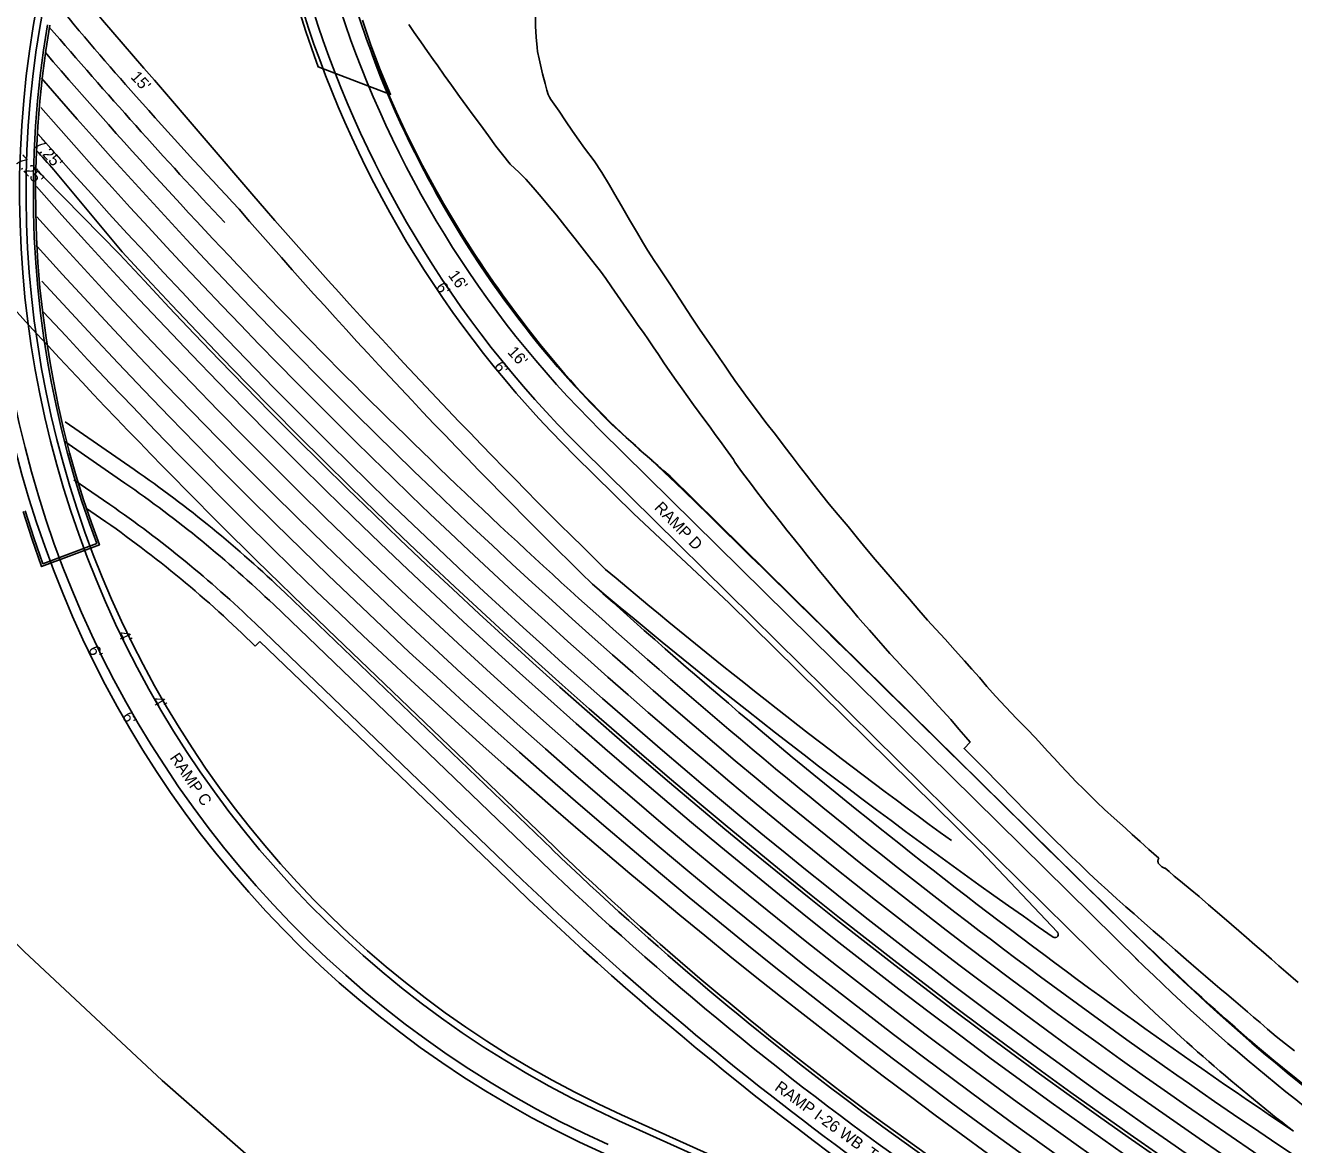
# Model space of a CAD drawing. Extents: x -5665 to 1997148, y 4 to 812485.
# Drawn here: x 1971429 to 1972202, y 795072 to 795754 of the extents above; entities that cross this region are included whole.
import ezdxf

# ---------------------------------------------------------------- set-up
doc = ezdxf.new("R2010")
doc.units = 0
for name, color, linetype in [('BR_CONCRETE', 7, 'Continuous'), ('RD_EX_RailRoad', 7, 'Continuous'), ('RD_EX_Road', 7, 'Continuous'), ('RD_PD_ALT1_TrvlWay', 7, 'Continuous'), ('RD_PD_Final_LnLine', 7, 'Continuous'), ('RD_PD_MedBWall', 7, 'Continuous'), ('RD_PD_PaveShd', 7, 'Continuous'), ('RD_SHT_TX', 7, 'Continuous')]:
    doc.layers.add(name, color=color, linetype=linetype)

msp = doc.modelspace()

# ---------------------------------------------------------------- linework, layer by layer
at = {"layer": 'BR_CONCRETE'}
for points in [[(1971634.55, 795757.25), (1971639.81, 795742.09), (1971645.43, 795727.05), (1971651.77, 795712.01), (1971607.64, 795728.69), (1971605.06, 795735.74), (1971600.01, 795750.42), (1971595.33, 795765.23)], [(1971427.6, 795457.68), (1971432.96, 795441.15), (1971438.9, 795424.1), (1971474.23, 795437.31), (1971469.3, 795450.73), (1971464.49, 795464.87), (1971460.05, 795479.14), (1971455.99, 795493.52), (1971452.32, 795508), (1971449.02, 795522.58), (1971446.11, 795537.24), (1971444.07, 795548.37), (1971441.63, 795563.56), (1971439.59, 795578.81), (1971437.93, 795594.1), (1971436.66, 795609.43), (1971435.79, 795624.79), (1971435.32, 795640.17), (1971435.23, 795655.56), (1971435.3, 795661.39), (1971435.74, 795676.92), (1971436.58, 795692.43), (1971437.81, 795707.91), (1971439.43, 795723.36), (1971441.45, 795738.75), (1971443.85, 795754.1)], [(1971428.84, 795458.07), (1971434.19, 795441.56), (1971439.69, 795425.78), (1971472.56, 795438.08), (1971468.07, 795450.29), (1971463.25, 795464.47), (1971458.8, 795478.77), (1971454.74, 795493.19), (1971451.05, 795507.7), (1971447.75, 795522.31), (1971444.83, 795537), (1971442.79, 795548.15), (1971440.35, 795563.37), (1971438.3, 795578.65), (1971436.63, 795593.98), (1971435.37, 795609.34), (1971434.49, 795624.74), (1971434.02, 795640.14), (1971433.93, 795655.56), (1971434, 795661.42), (1971434.44, 795676.97), (1971435.28, 795692.52), (1971436.52, 795708.03), (1971438.14, 795723.51), (1971440.16, 795738.94), (1971442.57, 795754.32)]]:
    msp.add_lwpolyline(points, dxfattribs=at)
at = {"layer": 'RD_EX_RailRoad'}
msp.add_lwpolyline([(1970768.64, 796132.97), (1970840.22, 796002.22), (1970871.33, 795945.04), (1970902.78, 795888.08), (1970934.57, 795831.3), (1970952.16, 795800.24), (1970967.81, 795773.45), (1970983.81, 795746.85), (1971000.15, 795720.46), (1971015.17, 795696.82), (1971080.56, 795598.9), (1971155.96, 795496.05), (1971262.73, 795364.94), (1971358.83, 795259.6), (1971428.31, 795189.39), (1971512.52, 795110.76), (1971575.1, 795055.94)], dxfattribs=at)
at = {"layer": 'RD_EX_Road'}
for points in [[(1972202.99, 795128.91), (1972197.53, 795133.14), (1972191.85, 795137.65), (1972186.64, 795142.05), (1972182.02, 795146.08), (1972178.11, 795149.44), (1972174.33, 795152.65), (1972170.09, 795156.24), (1972165.74, 795159.92), (1972161.68, 795163.37), (1972157.59, 795166.85), (1972153.17, 795170.6), (1972148.71, 795174.4), (1972144.52, 795178.02), (1972137.03, 795184.49), (1972130.15, 795190.47), (1972123.29, 795196.46), (1972116.91, 795202.04), (1972109.68, 795208.4), (1972105.18, 795212.33), (1972100.16, 795216.72), (1972094.76, 795221.51), (1972089.09, 795226.64), (1972083.34, 795231.93), (1972077.67, 795237.24), (1972072.22, 795242.41), (1972067.1, 795247.34), (1972062.06, 795252.25), (1972056.87, 795257.35), (1972051.98, 795262.19), (1972047.86, 795266.28), (1972043.68, 795270.47), (1972038.6, 795275.61), (1972032.58, 795281.75), (1972029.21, 795285.21), (1972025.59, 795288.94), (1972021.91, 795292.72), (1972014.91, 795299.86), (1972008.51, 795306.29), (1972001.53, 795313.25), (1972005.19, 795316.96), (1972002.54, 795320.11), (1971998.37, 795325.07), (1971993.46, 795330.77), (1971988.6, 795336.15), (1971983.74, 795341.44), (1971978.83, 795346.85), (1971973.91, 795352.22), (1971968.98, 795357.42), (1971964.33, 795362.3), (1971960.22, 795366.74), (1971956.27, 795371.11), (1971952.1, 795375.81), (1971947.88, 795380.6), (1971943.77, 795385.24), (1971939.83, 795389.73), (1971936.75, 795393.32), (1971932.4, 795398.47), (1971928.42, 795403.19), (1971924.47, 795407.9), (1971920.85, 795412.3), (1971917.2, 795416.78), (1971913.15, 795421.75), (1971909.19, 795426.63), (1971905.8, 795430.85), (1971902.3, 795435.25), (1971898.02, 795440.65), (1971893.51, 795446.33), (1971889.31, 795451.59), (1971885.43, 795456.44), (1971881.89, 795460.92), (1971878.52, 795465.27), (1971875.13, 795469.76), (1971871.8, 795474.18), (1971865.75, 795482.13), (1971861.78, 795487.75), (1971861.33, 795488.49), (1971860.83, 795489.47), (1971856.06, 795496.07), (1971852.88, 795500.39), (1971849.75, 795504.68), (1971846.59, 795509.01), (1971843.37, 795513.4), (1971840.02, 795517.96), (1971836.53, 795522.69), (1971833.05, 795527.52), (1971829.58, 795532.46), (1971825.94, 795537.62), (1971822.15, 795542.97), (1971818.5, 795548.23), (1971815.06, 795553.31), (1971811.91, 795558.01), (1971808.99, 795562.35), (1971805.96, 795566.73), (1971802.81, 795571.17), (1971799.84, 795575.37), (1971797.01, 795579.41), (1971793.78, 795584.1), (1971790.14, 795589.44), (1971786.52, 795594.71), (1971783.01, 795599.72), (1971779.71, 795604.17), (1971776.54, 795608.2), (1971772.84, 795612.94), (1971768.58, 795618.45), (1971764.38, 795623.83), (1971760.35, 795628.92), (1971756.54, 795633.73), (1971752.86, 795638.4), (1971748.51, 795643.69), (1971743.51, 795649.6), (1971738.68, 795655.21), (1971734.19, 795660.3), (1971730.28, 795664.27), (1971724.59, 795669.49), (1971719.94, 795675.3), (1971715.99, 795680.51), (1971711.46, 795686.64), (1971706.58, 795693.36), (1971702.21, 795699.33), (1971698.31, 795704.6), (1971693.86, 795710.69), (1971688.89, 795717.58), (1971684.51, 795723.68), (1971680.48, 795729.31), (1971677.72, 795733.24), (1971674.31, 795738.12), (1971670.25, 795743.95), (1971666.22, 795749.76), (1971662.88, 795754.58)], [(1972205.34, 795170.43), (1972197.82, 795176.94), (1972193.54, 795180.68), (1972188.95, 795184.68), (1972184.06, 795188.96), (1972178.86, 795193.5), (1972173.72, 795197.99), (1972168.99, 795202.09), (1972164.68, 795205.82), (1972157.2, 795212.24), (1972150.64, 795217.89), (1972144.82, 795222.88), (1972139.47, 795227.37), (1972134.7, 795231.25), (1972131.54, 795233.83), (1972129.7, 795235.37), (1972126.5, 795238.16), (1972124.22, 795240.18), (1972123.77, 795240.29), (1972123.33, 795240.44), (1972122.92, 795240.62), (1972122.51, 795240.83), (1972122.11, 795241.08), (1972121.29, 795241.76), (1972120.47, 795242.61), (1972120.17, 795243), (1972119.96, 795243.35), (1972119.85, 795243.66), (1972119.79, 795243.95), (1972119.76, 795244.24), (1972119.75, 795244.53), (1972119.77, 795244.81), (1972119.82, 795245.11), (1972119.92, 795245.45), (1972120.24, 795246.25), (1972114.21, 795251.7), (1972108.82, 795256.56), (1972104.07, 795260.83), (1972099.96, 795264.52), (1972092.98, 795270.79), (1972087.21, 795276.05), (1972082.42, 795280.53), (1972078.39, 795284.46), (1972074.45, 795288.4), (1972069.94, 795292.93), (1972064.15, 795298.92), (1972060.51, 795302.82), (1972056.39, 795307.3), (1972052.45, 795311.61), (1972047.16, 795317.37), (1972044.58, 795320.12), (1972040.17, 795324.7), (1972033.54, 795331.53), (1972026.91, 795338.48), (1972020.73, 795345.12), (1972015.38, 795351.08), (1972010.82, 795356.38), (1972006.33, 795361.52), (1972001.68, 795366.73), (1971996.17, 795372.85), (1971989.89, 795379.77), (1971984.26, 795385.97), (1971979.3, 795391.43), (1971973.96, 795397.47), (1971968.17, 795404.14), (1971962.7, 795410.47), (1971957.61, 795416.38), (1971952.52, 795422.33), (1971947.34, 795428.44), (1971942.04, 795434.79), (1971936.58, 795441.42), (1971930.73, 795448.45), (1971924.63, 795455.73), (1971919.26, 795462.24), (1971914.66, 795467.96), (1971910.09, 795473.8), (1971905.47, 795479.83), (1971901.04, 795485.62), (1971896.72, 795491.23), (1971891.86, 795497.52), (1971886.41, 795504.58), (1971880.69, 795512.03), (1971874.9, 795519.66), (1971869.84, 795526.43), (1971865.58, 795532.26), (1971861.76, 795537.62), (1971858.34, 795542.58), (1971855.34, 795546.97), (1971852.59, 795550.97), (1971849.13, 795555.95), (1971844.89, 795562.07), (1971840.23, 795568.86), (1971835.28, 795576.17), (1971830.33, 795583.66), (1971825.5, 795591.13), (1971821.22, 795597.69), (1971817.59, 795603.16), (1971814.74, 795607.47), (1971812.61, 795610.71), (1971810.75, 795613.53), (1971808.49, 795617.05), (1971805.44, 795622.13), (1971802.3, 795627.43), (1971797.51, 795635.58), (1971792.58, 795644.02), (1971788.48, 795651.04), (1971785.21, 795656.66), (1971780.67, 795664.39), (1971775.84, 795671.57), (1971770.08, 795679.26), (1971766.63, 795684.05), (1971762.76, 795689.57), (1971758.47, 795695.84), (1971754.48, 795701.72), (1971749.55, 795708.94), (1971748.61, 795710.29), (1971748.19, 795711), (1971747.78, 795711.96), (1971746.98, 795714.61), (1971745.95, 795718.68), (1971744.44, 795724.61), (1971742.34, 795733.65), (1971741.44, 795738.06), (1971741.15, 795740.48), (1971740.59, 795746.9), (1971740.15, 795753.55), (1971740.09, 795759.95)], [(1972208.47, 795108.39), (1972201.83, 795113.73), (1972195.78, 795118.63), (1972190.51, 795122.93), (1972185.36, 795127.2), (1972180.48, 795131.34), (1972177.35, 795133.99), (1972175.69, 795135.43), (1972172.24, 795138.43), (1972166.76, 795143.23), (1972160.87, 795148.41), (1972154.61, 795153.96), (1972150.83, 795157.37), (1972146.54, 795161.29), (1972141.73, 795165.71), (1972136.97, 795170.12), (1972132.83, 795173.98), (1972126.38, 795180.08), (1972121.57, 795184.71), (1972117.55, 795188.57), (1972112.98, 795192.96), (1972106.54, 795199.17), (1972102.69, 795202.91), (1972098.5, 795206.99), (1972093.98, 795211.42), (1972089.13, 795216.19), (1972084.21, 795221.04), (1972079.48, 795225.69), (1972074.93, 795230.14), (1972070.58, 795234.39), (1972066.25, 795238.62), (1972061.75, 795243.01), (1972057.09, 795247.57), (1972052.27, 795252.3), (1972047.12, 795257.36), (1972041.46, 795262.94), (1972035.3, 795269.02), (1972028.63, 795275.61), (1972021.63, 795282.54), (1972014.45, 795289.61), (1972007.11, 795296.83), (1971999.59, 795304.21), (1971992.01, 795311.63), (1971984.48, 795319.02), (1971977, 795326.36), (1971969.58, 795333.66), (1971962.15, 795340.97), (1971954.65, 795348.35), (1971947.08, 795355.78), (1971939.45, 795363.28), (1971931.75, 795370.85), (1971923.98, 795378.51), (1971916.13, 795386.25), (1971908.2, 795394.07), (1971900.36, 795401.81), (1971892.77, 795409.28), (1971885.44, 795416.49), (1971878.36, 795423.44), (1971871.13, 795430.52), (1971863.37, 795438.13), (1971855.05, 795446.28), (1971846.2, 795454.97), (1971837.83, 795463.17), (1971830.96, 795469.87), (1971825.61, 795475.08), (1971818.89, 795481.54), (1971814.43, 795485.78), (1971811.29, 795488.73), (1971806.89, 795492.7), (1971801.09, 795497.86), (1971795.5, 795502.84), (1971790.49, 795507.31), (1971786.74, 795510.76), (1971784.13, 795513.3), (1971781.27, 795516.16), (1971777.88, 795519.61), (1971773.54, 795524.14), (1971768.57, 795529.39), (1971765.38, 795532.78), (1971763.94, 795534.32), (1971761.71, 795536.78), (1971758.26, 795540.65), (1971753.61, 795545.97), (1971748.06, 795552.42), (1971743.48, 795557.86), (1971740.03, 795562.1), (1971736.92, 795566.03), (1971733.87, 795569.97), (1971729.99, 795575.04), (1971725.35, 795581.14), (1971721.23, 795586.62), (1971717.72, 795591.39), (1971714.02, 795596.58), (1971710.03, 795602.34), (1971705.82, 795608.6), (1971701.52, 795615.14), (1971697.87, 795620.85), (1971694.8, 795625.83), (1971691.16, 795631.84), (1971686.95, 795638.89), (1971683.25, 795645.2), (1971680.19, 795650.58), (1971677.45, 795655.56), (1971674.91, 795660.33), (1971672.24, 795665.39), (1971669.41, 795670.83), (1971666.52, 795676.52), (1971663.6, 795682.45), (1971660.63, 795688.56), (1971657.61, 795694.88), (1971654.54, 795701.62), (1971651.45, 795708.73), (1971648.49, 795715.79), (1971645.68, 795722.74), (1971643, 795729.69), (1971640.57, 795736.24), (1971639.23, 795739.89), (1971639.01, 795740.48)]]:
    msp.add_lwpolyline(points, dxfattribs=at)
at = {"layer": 'RD_PD_ALT1_TrvlWay'}
for p, q in [((1971779.64, 795507.29), (1972107.79, 795183.82)), ((1971453.08, 795500.31), (1971489.67, 795475.03)), ((1972094.93, 795174.03), (1971768.41, 795495.9)), ((1971458.6, 795477.05), (1971480.58, 795461.86)), ((1971580.47, 795400.88), (1971743.18, 795244.69)), ((1971569.39, 795389.34), (1971732.1, 795233.15)), ((1971790.98, 795086.26), (1972145.53, 794926.28))]:
    msp.add_line(p, q, dxfattribs=at)
for centre, radius, start, end in [((1972226.58, 795960.7), 652.66, 167.91315, 225.41147), ((1972226.58, 795960.7), 636.66, 170.70317, 225.41147), ((1972046.23, 795651.96), 636.62, 156.21044, 245.71509), ((1972046.23, 795651.96), 620.62, 156.21044, 245.71509), ((1972855.69, 796921.19), 1820, 219.26396, 221.68841), ((1974296, 798203.94), 3748.72, 221.68841, 223.11151), ((1974296, 798203.94), 3808.72, 221.35099, 236.97136), ((1974296, 798203.94), 3830.72, 221.69794, 243.9112), ((1974398.08, 798103.05), 3757.03, 220.92379, 225.71558), ((1974296, 798203.94), 3878.72, 222.58465, 241.30888), ((1971073.56, 794872.81), 732, 46.17145, 55.35655), ((1971073.56, 794872.81), 716, 46.17145, 55.35655), ((1974296, 798203.94), 3760.72, 227.90275, 236.17378), ((1973117.1, 796675.98), 1984, 226.17145, 243.9112), ((1973117.1, 796675.98), 2000, 226.17145, 241.45743), ((1972948.57, 796040.02), 1200, 225.41147, 237.12717), ((1972948.57, 796040.02), 1216, 225.41147, 232.15338)]:
    msp.add_arc(centre, radius, start, end, dxfattribs=at)
at = {"layer": 'RD_PD_Final_LnLine'}
for radius, start, end in [(3760.72, 220.66614, 223.11151), (3772.72, 220.82697, 227.89927), (3784.72, 220.98219, 236.97136), (3796.72, 221.18106, 236.97136), (3842.72, 221.90557, 243.9112), (3854.72, 222.10892, 243.9112), (3866.72, 222.36815, 243.9112), (3772.72, 227.89927, 236.97136)]:
    msp.add_arc((1974296, 798203.94), radius, start, end, dxfattribs=at)
at = {"layer": 'RD_PD_MedBWall'}
for p, q in [((1971486.53, 795614.58), (1971440.84, 795660.92)), ((1971446.44, 795665.91), (1971488.03, 795615.91))]:
    msp.add_line(p, q, dxfattribs=at)
for radius, start in [(3820.72, 222.66541), (3818.72, 222.66592)]:
    msp.add_arc((1974296, 798203.94), radius, start, 243.9112, dxfattribs=at)
at = {"layer": 'RD_PD_PaveShd'}
for p, q in [((1971507.76, 795720.72), (1971568.41, 795649.85)), ((1971453.36, 795512.27), (1971495.36, 795483.25)), ((1971764.19, 795491.62), (1971799.86, 795456.47)), ((1972114.81, 795190.94), (1971822.32, 795479.26)), ((1971466.3, 795459.57), (1971474.89, 795453.64)), ((1971799.86, 795456.47), (1971858.24, 795401.73)), ((1971587.39, 795408.1), (1971750.1, 795251.91)), ((1971858.24, 795401.73), (1972011.44, 795250.71)), ((1971613.52, 795385.79), (1971751.49, 795253.35)), ((1971572.09, 795378.42), (1971569.24, 795375.53)), ((1971572.09, 795378.42), (1971727.94, 795228.82)), ((1972011.44, 795250.71), (1972058.4, 795201.23)), ((1971792.63, 795089.9), (1972007.59, 794992.91))]:
    msp.add_line(p, q, dxfattribs=at)
for centre, radius, start, end in [((1972226.58, 795960.7), 658.66, 167.91315, 225.41147), ((1972226.58, 795960.7), 627.43, 173.70525, 208.85724), ((1972855.69, 796921.19), 1805, 211.88652, 221.68841), ((1972046.23, 795651.96), 642.62, 156.21044, 245.71509), ((1972046.23, 795651.96), 616.62, 156.21044, 245.71509), ((1974296, 798203.94), 3815.97, 221.44705, 221.69067), ((1974296, 798203.94), 3823.47, 221.57883, 221.69067), ((1972271.31, 795985.34), 678.5, 208.85724, 221.68144), ((1974398.08, 798103.05), 3745.03, 220.92379, 225.70896), ((1974296, 798203.94), 3890.72, 221.64292, 226.41296), ((1972190.25, 795924.25), 577.4, 222.50253, 230.41518), ((1971073.56, 794872.81), 742, 46.17145, 55.35655), ((1971073.56, 794872.81), 706, 45.40382, 55.35655), ((1974194.95, 798281.36), 3740.57, 229.84701, 233.95222), ((1974194.95, 798281.36), 3752.57, 229.84039, 235.24659), ((1973117.1, 796675.98), 1974, 226.17145, 241.02073), ((1973117.1, 796675.98), 1972, 226.17145, 241.02073), ((1973117.1, 796675.98), 2006, 226.17145, 236.56111), ((1972056.96, 795199.85), 2, 235.24659, 55.24659), ((1972996.53, 796085.43), 1256, 225.41147, 239.13377)]:
    msp.add_arc(centre, radius, start, end, dxfattribs=at)

# ---------------------------------------------------------------- texts
at = {"layer": 'RD_SHT_TX'}
for s, rotation, p in [("15'", 312.68663, (1971492.8, 795722.29)), ("7.25'", 312.71108, (1971433.7, 795681)), ("7.25'", 312.71108, (1971422.2, 795671.03)), ("16'", 305.66358, (1971686.56, 795601.69)), ("6'", 305.66358, (1971678.92, 795594.35)), ("16'", 312.49109, (1971722.63, 795554.52)), ("6'", 305.66358, (1971714.44, 795546.16)), ('RAMP D', 314.2929, (1971812.25, 795459.58)), ("4'", 294.41626, (1971485.36, 795383.24)), ("6'", 295.55454, (1971467.2, 795373.76)), ("4'", 300.96466, (1971506.25, 795342.7)), ("6'", 302.10293, (1971487.71, 795332.8)), ('RAMP C', 304.38956, (1971516.83, 795307.49)), (' RAMP I-26 WB  TO I-126 EB', 324.11706, (1971883.37, 795106.88))]:
    msp.add_text(s, height=7, rotation=rotation, dxfattribs=at).set_placement(p)

doc.saveas('drawing.dxf')
